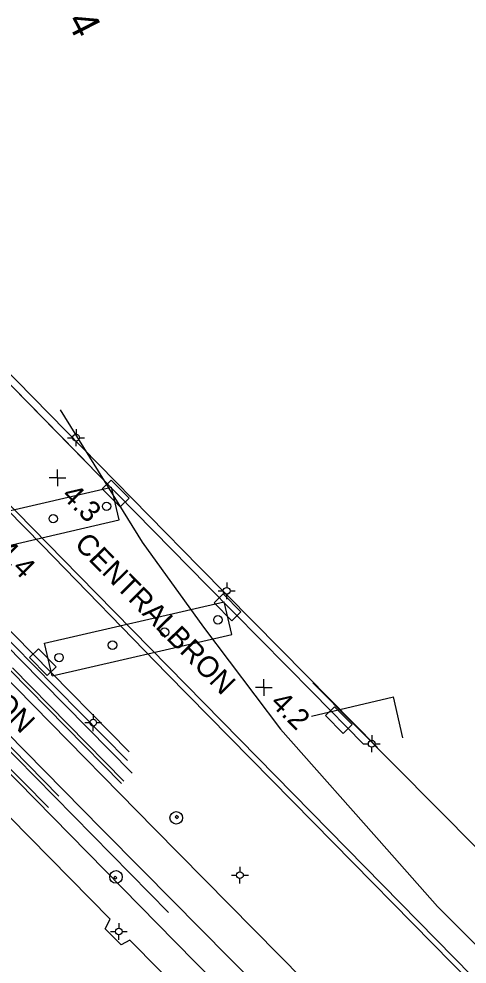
# Model space of a CAD drawing. Extents: x 1596643 to 1597288, y 13057194 to 13057957.
# Drawn here: x 1597047.6 to 1597101, y 13057293 to 13057405.5 of the extents above; entities that cross this region are included whole.
import ezdxf

# ---------------------------------------------------------------- set-up
doc = ezdxf.new("R2010")
doc.units = 0
for name, color, linetype in [('A spårmitt L', 7, 'Continuous'), ('BAS belysningsstolpe P', 7, 'Continuous'), ('BAS bro kantbalk ej def L', 7, 'Continuous'), ('BAS dagvatten brunn P', 7, 'Continuous'), ('BAS fastighetsgräns samfällighet L', 7, 'Continuous'), ('BAS jvg-bro kantbalk L', 7, 'Continuous'), ('BAS Level 16', 7, 'Continuous'), ('BAS Level 36', 7, 'Continuous'), ('BAS markytetext T', 7, 'Continuous'), ('BAS staket plank lågt L', 7, 'Continuous'), ('BAS väg T', 7, 'Continuous'), ('BAS väg-bro kantbalk L', 7, 'Continuous'), ('BAS väg-bro pelare stöd L', 7, 'Continuous'), ('BAS vägbanekant L', 7, 'Continuous'), ('E ktl sträva stag fundament L', 7, 'Continuous'), ('E ktlstolpe normal centrum P', 7, 'Continuous')]:
    doc.layers.add(name, color=color, linetype=linetype)

msp = doc.modelspace()

# ---------------------------------------------------------------- linework, layer by layer
at = {"layer": 'A spårmitt L'}
for points in [[(1596887.99, 13057492.75), (1596889.66, 13057490.52), (1596900.09, 13057476.78), (1596906.53, 13057469.46), (1596928.33, 13057446.66), (1596936.9, 13057437.94), (1596957.34, 13057417.35), (1597001.93, 13057371.99), (1597034.88, 13057338.51), (1597063.76, 13057309.15)], [(1596933.8, 13057434.84), (1596974.46, 13057393.51), (1596978.36, 13057389.55), (1596998.7, 13057368.85), (1597057.44, 13057309.15)], [(1597169.86, 13057193.86), (1597135.93, 13057229.36), (1597100.08, 13057266.04), (1597062.36, 13057304.16), (1597057.44, 13057309.15)], [(1597063.76, 13057309.15), (1597111.15, 13057261.14), (1597142.08, 13057229.69), (1597153.95, 13057217.4)]]:
    msp.add_lwpolyline(points, dxfattribs=at)
at = {"layer": 'BAS belysningsstolpe P'}
for p, q in [((1597054.41, 13057356.7), (1597054.41, 13057356.1)), ((1597054.41, 13057356.7), (1597054.41, 13057356.1)), ((1597053.41, 13057355.7), (1597054.01, 13057355.7)), ((1597053.41, 13057355.7), (1597054.01, 13057355.7)), ((1597054.41, 13057354.7), (1597054.41, 13057355.3)), ((1597054.41, 13057354.7), (1597054.41, 13057355.3)), ((1597054.81, 13057355.7), (1597055.41, 13057355.7)), ((1597054.81, 13057355.7), (1597055.41, 13057355.7)), ((1597072.35, 13057338.46), (1597072.35, 13057337.86)), ((1597072.35, 13057338.46), (1597072.35, 13057337.86)), ((1597071.35, 13057337.46), (1597071.95, 13057337.46)), ((1597071.35, 13057337.46), (1597071.95, 13057337.46)), ((1597072.75, 13057337.46), (1597073.35, 13057337.46)), ((1597072.75, 13057337.46), (1597073.35, 13057337.46)), ((1597072.35, 13057336.46), (1597072.35, 13057337.06)), ((1597072.35, 13057336.46), (1597072.35, 13057337.06)), ((1597056.44, 13057322.78), (1597056.44, 13057322.18)), ((1597056.44, 13057322.78), (1597056.44, 13057322.18)), ((1597055.44, 13057321.78), (1597056.04, 13057321.78)), ((1597055.44, 13057321.78), (1597056.04, 13057321.78)), ((1597056.84, 13057321.78), (1597057.44, 13057321.78)), ((1597056.84, 13057321.78), (1597057.44, 13057321.78)), ((1597056.44, 13057320.78), (1597056.44, 13057321.39)), ((1597056.44, 13057320.78), (1597056.44, 13057321.39)), ((1597088.62, 13057319.27), (1597089.22, 13057319.27)), ((1597088.62, 13057319.27), (1597089.22, 13057319.27)), ((1597089.62, 13057320.27), (1597089.62, 13057319.67)), ((1597089.62, 13057320.27), (1597089.62, 13057319.67)), ((1597090.02, 13057319.27), (1597090.62, 13057319.27)), ((1597090.02, 13057319.27), (1597090.62, 13057319.27)), ((1597089.62, 13057318.27), (1597089.62, 13057318.87)), ((1597089.62, 13057318.27), (1597089.62, 13057318.87)), ((1597073.93, 13057304.62), (1597073.93, 13057304.02)), ((1597073.93, 13057304.62), (1597073.93, 13057304.02)), ((1597072.93, 13057303.62), (1597073.53, 13057303.62)), ((1597072.93, 13057303.62), (1597073.53, 13057303.62)), ((1597074.33, 13057303.62), (1597074.93, 13057303.62)), ((1597074.33, 13057303.62), (1597074.93, 13057303.62)), ((1597073.93, 13057302.62), (1597073.93, 13057303.22)), ((1597073.93, 13057302.62), (1597073.93, 13057303.22)), ((1597059.51, 13057297.92), (1597059.51, 13057297.32)), ((1597059.51, 13057297.92), (1597059.51, 13057297.32)), ((1597058.51, 13057296.92), (1597059.11, 13057296.92)), ((1597058.51, 13057296.92), (1597059.11, 13057296.92)), ((1597059.91, 13057296.92), (1597060.51, 13057296.92)), ((1597059.91, 13057296.92), (1597060.51, 13057296.92)), ((1597059.51, 13057295.92), (1597059.51, 13057296.52)), ((1597059.51, 13057295.92), (1597059.51, 13057296.52))]:
    msp.add_line(p, q, dxfattribs=at)
for centre in [(1597054.41, 13057355.7), (1597054.41, 13057355.7), (1597072.35, 13057337.46), (1597072.35, 13057337.46), (1597056.44, 13057321.78), (1597056.44, 13057321.78), (1597089.62, 13057319.27), (1597089.62, 13057319.27), (1597073.93, 13057303.62), (1597073.93, 13057303.62), (1597059.51, 13057296.92), (1597059.51, 13057296.92)]:
    msp.add_circle(centre, 0.4, dxfattribs=at)
at = {"layer": 'BAS bro kantbalk ej def L'}
for p, q in [((1597034.41, 13057342.84), (1597047.77, 13057329.3)), ((1597046.84, 13057328.29), (1597060.1, 13057314.81)), ((1597047.77, 13057329.3), (1597061.08, 13057315.75)), ((1597059.82, 13057314.53), (1597046.56, 13057328.01)), ((1597065.42, 13057299.19), (1597038.82, 13057326.22)), ((1597052.37, 13057313.03), (1597039.11, 13057326.5)), ((1597051.11, 13057311.67), (1597037.78, 13057325.22))]:
    msp.add_line(p, q, dxfattribs=at)
for points in [[(1597082.62, 13057326.5), (1597107.15, 13057301.8), (1597126.54, 13057281.98), (1597136.53, 13057271.8)], [(1597125.05, 13057230.54), (1597087.53, 13057268.72), (1597086.31, 13057268.28), (1597084.58, 13057270.11), (1597085.09, 13057271.35), (1597067.86, 13057288.79), (1597060.82, 13057295.89), (1597059.79, 13057295.32), (1597057.86, 13057297.22), (1597058.48, 13057298.37), (1597044.11, 13057312.93), (1597034.13, 13057323.01), (1597033.23, 13057322.45), (1597031.34, 13057324.26), (1597031.74, 13057325.45)]]:
    msp.add_lwpolyline(points, dxfattribs=at)
at = {"layer": 'BAS dagvatten brunn P'}
for p, q in [((1597059.13, 13057349.06), (1597059.13, 13057349.06)), ((1597059.13, 13057349.06), (1597059.13, 13057349.06)), ((1597072.44, 13057335.51), (1597072.44, 13057335.51)), ((1597072.44, 13057335.51), (1597072.44, 13057335.51)), ((1597050.45, 13057328.98), (1597050.45, 13057328.98)), ((1597050.45, 13057328.98), (1597050.45, 13057328.98)), ((1597085.71, 13057322.08), (1597085.71, 13057322.08)), ((1597085.71, 13057322.08), (1597085.71, 13057322.08))]:
    msp.add_line(p, q, dxfattribs=at)
for points in [[(1597057.54, 13057349.6), (1597059.65, 13057347.47), (1597060.72, 13057348.52), (1597058.61, 13057350.66)], [(1597057.54, 13057349.6), (1597059.65, 13057347.47), (1597060.72, 13057348.52), (1597058.61, 13057350.66)], [(1597070.86, 13057336.05), (1597072.96, 13057333.91), (1597074.03, 13057334.96), (1597071.92, 13057337.1)], [(1597070.86, 13057336.05), (1597072.96, 13057333.91), (1597074.03, 13057334.96), (1597071.92, 13057337.1)], [(1597052.04, 13057328.44), (1597049.93, 13057330.57), (1597048.86, 13057329.52), (1597050.97, 13057327.38)], [(1597052.04, 13057328.44), (1597049.93, 13057330.57), (1597048.86, 13057329.52), (1597050.97, 13057327.38)], [(1597084.12, 13057322.63), (1597086.23, 13057320.49), (1597087.3, 13057321.54), (1597085.19, 13057323.68)], [(1597084.12, 13057322.63), (1597086.23, 13057320.49), (1597087.3, 13057321.54), (1597085.19, 13057323.68)]]:
    msp.add_lwpolyline(points, close=True, dxfattribs=at)
at = {"layer": 'BAS fastighetsgräns samfällighet L'}
msp.add_lwpolyline([(1597052.53, 13057359.03), (1597062.28, 13057343.25), (1597069.57, 13057333.14), (1597078.77, 13057321.01), (1597091.41, 13057306.72), (1597097.45, 13057299.9), (1597097.45, 13057299.9), (1597111.94, 13057285.43), (1597118.53, 13057279.24), (1597129.16, 13057269.41), (1597129.54, 13057268.99), (1597137.19, 13057261.6), (1597138.96, 13057260.07)], dxfattribs=at)
at = {"layer": 'BAS jvg-bro kantbalk L'}
for p, q in [((1597045.33, 13057364.51), (1597057.12, 13057352.52)), ((1597057.12, 13057352.52), (1597069.13, 13057340.29)), ((1597038.05, 13057340.12), (1597049.26, 13057328.7)), ((1597069.13, 13057340.29), (1597081.84, 13057327.41)), ((1597049.26, 13057328.7), (1597060.53, 13057317.26))]:
    msp.add_line(p, q, dxfattribs=at)
at = {"layer": 'BAS Level 16'}
for p, q in [((1597052.19, 13057350.92), (1597052.19, 13057351.92)), ((1597052.19, 13057350.92), (1597052.19, 13057351.92)), ((1597052.19, 13057350.92), (1597051.19, 13057350.92)), ((1597052.19, 13057350.92), (1597051.19, 13057350.92)), ((1597052.19, 13057350.92), (1597053.19, 13057350.92)), ((1597052.19, 13057350.92), (1597052.19, 13057349.92)), ((1597052.19, 13057350.92), (1597053.19, 13057350.92)), ((1597052.19, 13057350.92), (1597052.19, 13057349.92)), ((1597076.77, 13057325.96), (1597075.77, 13057325.96)), ((1597076.77, 13057325.96), (1597075.77, 13057325.96)), ((1597076.77, 13057325.96), (1597076.77, 13057326.96)), ((1597076.77, 13057325.96), (1597076.77, 13057326.96)), ((1597076.77, 13057325.96), (1597077.77, 13057325.96)), ((1597076.77, 13057325.96), (1597076.77, 13057324.96)), ((1597076.77, 13057325.96), (1597077.77, 13057325.96)), ((1597076.77, 13057325.96), (1597076.77, 13057324.96))]:
    msp.add_line(p, q, dxfattribs=at)
at = {"layer": 'BAS staket plank lågt L'}
for points in [[(1597039.14, 13057323.23), (1597066.17, 13057295.73)], [(1597129.45, 13057231.15), (1597099.09, 13057262.33), (1597066.17, 13057295.73), (1597039.14, 13057323.23)]]:
    msp.add_lwpolyline(points, dxfattribs=at)
at = {"layer": 'BAS väg-bro kantbalk L'}
msp.add_lwpolyline([(1597090.3, 13057318.81), (1597081.84, 13057327.41)], dxfattribs=at)
at = {"layer": 'BAS väg-bro pelare stöd L'}
for p, q in [((1597037.25, 13057344.86), (1597058.62, 13057349.81)), ((1597059.53, 13057345.92), (1597058.62, 13057349.81)), ((1597038.15, 13057340.97), (1597059.53, 13057345.92)), ((1597050.67, 13057331.23), (1597072.04, 13057336.18)), ((1597072.95, 13057332.29), (1597072.04, 13057336.18)), ((1597051.58, 13057327.34), (1597072.95, 13057332.29)), ((1597051.58, 13057327.34), (1597050.67, 13057331.23)), ((1597082.47, 13057322.57), (1597092.21, 13057324.86)), ((1597093.34, 13057319.99), (1597092.21, 13057324.86))]:
    msp.add_line(p, q, dxfattribs=at)
for centre in [(1597058.05, 13057347.53), (1597051.69, 13057346.06), (1597071.31, 13057334.02), (1597064.95, 13057332.55), (1597058.75, 13057331), (1597052.39, 13057329.52)]:
    msp.add_circle(centre, 0.5, dxfattribs=at)
at = {"layer": 'BAS vägbanekant L'}
for p, q in [((1597057.18, 13057351.18), (1597045.04, 13057363.54)), ((1597070.08, 13057338.08), (1597057.18, 13057351.18)), ((1597049.17, 13057330.06), (1597037.91, 13057341.52)), ((1597082.61, 13057325.35), (1597070.08, 13057338.08)), ((1597060.73, 13057318.32), (1597049.17, 13057330.06))]:
    msp.add_line(p, q, dxfattribs=at)
for points in [[(1597133.45, 13057259.15), (1597054.73, 13057339.3), (1596995.85, 13057399.37), (1596990.43, 13057405.03), (1596987.37, 13057408.32), (1596983.64, 13057412.32), (1596981.85, 13057414.31), (1596980.19, 13057416.21), (1596978.63, 13057418.01), (1596978.19, 13057418.58), (1596977.38, 13057419.58), (1596976.06, 13057421.35), (1596974.48, 13057423.49), (1596972.43, 13057426.49), (1596969.83, 13057430.51), (1596968.37, 13057432.85)], [(1596968.37, 13057431.55), (1596968.41, 13057431.49), (1596970.97, 13057427.58), (1596973.44, 13057423.94), (1596974.8, 13057422.08), (1596976.84, 13057419.44), (1596978.38, 13057417.44), (1596980.14, 13057415.39), (1596981.65, 13057413.62), (1596983.9, 13057411.12), (1596986.84, 13057408.01), (1596993.05, 13057401.31), (1597001.07, 13057393.12), (1597017.41, 13057376.51), (1597028.56, 13057365.16), (1597039.89, 13057353.55), (1597050.38, 13057342.91), (1597065.28, 13057327.59), (1597082.63, 13057309.92), (1597099.19, 13057293.12), (1597132.62, 13057259.15)], [(1597056.32, 13057352.06), (1597045.04, 13057363.54)], [(1597088.61, 13057319.25), (1597082.61, 13057325.35)]]:
    msp.add_lwpolyline(points, dxfattribs=at)
at = {"layer": 'E ktl sträva stag fundament L'}
for points in [[(1597066.23, 13057310.55), (1597066.44, 13057310.35), (1597066.6, 13057310.52), (1597066.39, 13057310.72), (1597066.23, 13057310.55)], [(1597059.07, 13057303.51), (1597059.27, 13057303.3), (1597059.11, 13057303.14), (1597058.91, 13057303.35), (1597059.07, 13057303.51)]]:
    msp.add_lwpolyline(points, dxfattribs=at)
at = {"layer": 'E ktlstolpe normal centrum P'}
for centre in [(1597066.34, 13057310.45), (1597066.34, 13057310.45), (1597059.17, 13057303.41), (1597059.17, 13057303.41)]:
    msp.add_circle(centre, 0.75, dxfattribs=at)

# ---------------------------------------------------------------- texts
at = {"layer": 'BAS Level 36'}
msp.add_text('4', height=3.5, rotation=296.9611, dxfattribs=at).set_placement((1597053.23, 13057405.37))
at = {"layer": 'BAS markytetext T'}
for s, p in [('4.3', (1597052.58, 13057348.71)), ('4.4', (1597044.74, 13057342.04)), ('4.2', (1597077.44, 13057324.01))]:
    msp.add_text(s, height=2.5, rotation=315, dxfattribs=at).set_placement(p)
at = {"layer": 'BAS väg T'}
for s, rotation, p in [('NORRSTRÖMSBRON', 314.541, (1597024.23, 13057344.43)), ('CENTRALBRON', 314.604, (1597054.1, 13057342.9))]:
    msp.add_text(s, height=2.5, rotation=rotation, dxfattribs=at).set_placement(p)

doc.saveas('drawing.dxf')
